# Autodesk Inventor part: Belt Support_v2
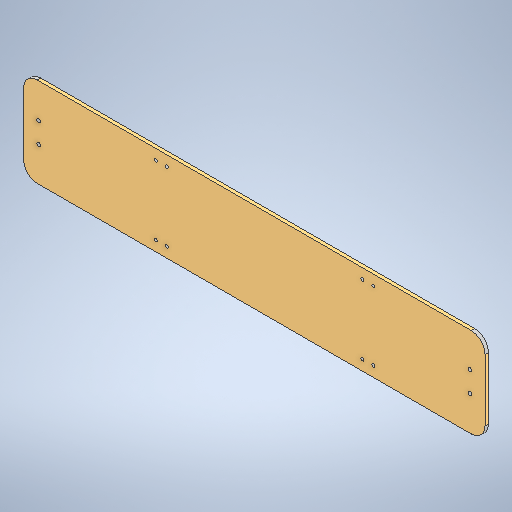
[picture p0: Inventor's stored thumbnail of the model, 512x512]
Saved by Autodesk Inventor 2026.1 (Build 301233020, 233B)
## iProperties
Created: 2026-10
Part Number: Belt Support_v2
Material: Generic
Document SubType Name: Modeling
Designer: hp
Density: 1 g/cm^3
Appearance: Default
Author: hp
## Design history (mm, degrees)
sketch "Sketch1"
  geometry: L1 (0, 0)-(670, 0); L2 (670, 0)-(670, 130); L3 (670, 130)-(0, 130); L4 (0, 130)-(0, 0)
  constraints: 8 end point, 2 parallel, 1 horizontal, 1 perpendicular
  dimensions: "d0" = 670 distance of L3.end L2.end; "d1" = 130 distance of L2.end L1.end
extrude "Extrusion1" new body sketch "Sketch1" distance "d2" = 5; taper "d3" = 0 deg
fillet "Fillet1" dims "d4" = 20
sketch "Sketch2"
  geometry: 4 further points
hole "Hole1" sketch "Sketch2" at (648, 50), (648, 80), (22, 50), (22, 80) diameter "d5" = 5.5; stored, may be unused: countersink angle "d9" = 90 deg, drill point angle "d11" = 0 deg; dims "d6" = 6, "d7" = 4, "d8" = 2, "d10" = 8
sketch "Sketch3"
  geometry: 8 further points
hole "Hole2" sketch "Sketch3" at (-508, 15), (-492, 15), (-208, 15), (-192, 15), (-508, 115), (-492, 115), (-208, 115), (-192, 115) diameter "d12" = 4.5; stored, may be unused: countersink angle "d16" = 90 deg, drill point angle "d18" = 0 deg; dims "d13" = 6, "d14" = 4, "d15" = 2, "d17" = 8
body "Solid1"
